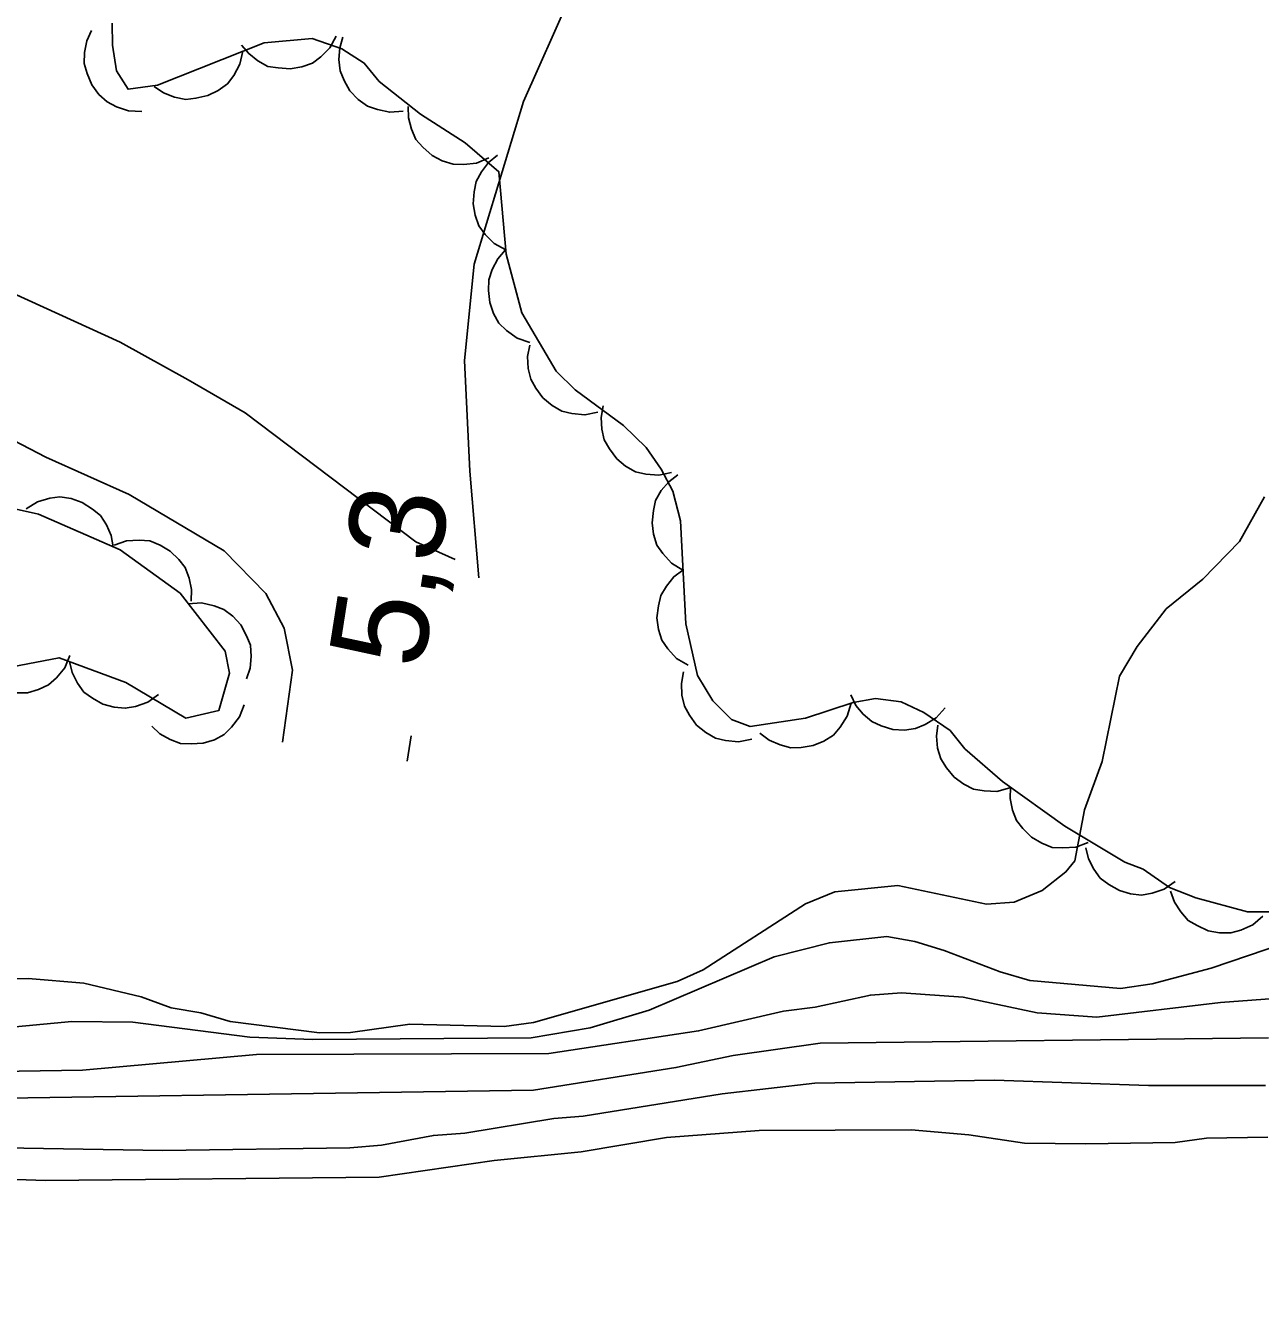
# Model space of a CAD drawing. Extents: x 282461 to 284471, y 5554090 to 5557646.
# Drawn here: x 283663.01 to 283701.79, y 5554643.6 to 5554684.09 of the extents above; entities that cross this region are included whole.
import ezdxf

# ---------------------------------------------------------------- set-up
doc = ezdxf.new("R2010")
doc.units = 0
for name, color, linetype in [('Niveau 1', 7, 'Continuous'), ('Niveau 2', 7, 'Continuous'), ('Niveau 21', 7, 'Continuous'), ('Niveau 22', 7, 'Continuous'), ('Niveau 3', 7, 'Continuous'), ('Niveau 4', 7, 'Continuous'), ('Niveau 44', 7, 'Continuous')]:
    doc.layers.add(name, color=color, linetype=linetype)

msp = doc.modelspace()

# ---------------------------------------------------------------- linework, layer by layer
at = {"layer": 'Niveau 1'}
for points in [[(283701.92, 5554669.28), (283701.13, 5554667.88), (283699.98, 5554666.7), (283698.83, 5554665.76), (283697.92, 5554664.58), (283697.36, 5554663.65), (283696.82, 5554660.97), (283696.26, 5554659.45), (283695.96, 5554657.85)], [(283695.96, 5554657.85), (283695.68, 5554657.5), (283694.93, 5554656.91), (283694.06, 5554656.55), (283693.19, 5554656.48), (283690.4, 5554657.07), (283688.42, 5554656.87), (283687.5, 5554656.5), (283684.28, 5554654.42), (283683.47, 5554654.06), (283678.96, 5554652.77), (283678.03, 5554652.64), (283675.07, 5554652.71), (283673.21, 5554652.45), (283672.23, 5554652.44), (283669.43, 5554652.8), (283668.5, 5554653.07), (283667.57, 5554653.23), (283666.63, 5554653.57), (283664.83, 5554654), (283663.08, 5554654.15), (283662.09, 5554654.13)]]:
    msp.add_lwpolyline(points, dxfattribs=at)
at = {"layer": 'Niveau 2'}
for points in [[(283686.52, 5554654.83), (283688.25, 5554655.27), (283690.05, 5554655.47), (283690.93, 5554655.31), (283691.86, 5554655.03), (283693.62, 5554654.36), (283694.55, 5554654.09), (283697.4, 5554653.84), (283698.39, 5554653.98), (283700.24, 5554654.47), (283702.56, 5554655.26)], [(283661.55, 5554652.53), (283664.45, 5554652.8), (283666.37, 5554652.78), (283670.04, 5554652.31), (283672.02, 5554652.23), (283678.88, 5554652.28), (283680.74, 5554652.6), (283682.59, 5554653.15), (283686.52, 5554654.83)], [(283702.51, 5554653.54), (283700.54, 5554653.4), (283696.65, 5554652.93), (283694.78, 5554653.07), (283692.45, 5554653.56), (283690.52, 5554653.7), (283689.54, 5554653.63), (283687.8, 5554653.25), (283686.81, 5554653.12), (283684.14, 5554652.5), (283679.44, 5554651.79), (283670.25, 5554651.76), (283664.79, 5554651.27), (283654.84, 5554651.11)], [(283618.87, 5554643.6), (283624.75, 5554643.69), (283625.68, 5554643.76), (283628.35, 5554644.21), (283631.08, 5554644.89), (283634.73, 5554646.06), (283636.53, 5554646.49), (283639.19, 5554647.35), (283641.63, 5554647.97), (283648.59, 5554649.12), (283649.58, 5554649.14), (283650.51, 5554649.27), (283656.84, 5554650.3), (283678.96, 5554650.64), (283683.43, 5554651.35), (283685.23, 5554651.73), (283687.96, 5554652.12), (283702.05, 5554652.28)], [(283639.04, 5554645.5), (283639.91, 5554645.98), (283641.76, 5554646.71), (283642.63, 5554646.96), (283648.27, 5554647.74), (283651.93, 5554648.38), (283653.85, 5554648.53), (283658.57, 5554648.6), (283660.43, 5554648.86), (283667.31, 5554648.74), (283673.19, 5554648.83), (283674.18, 5554648.91), (283675.81, 5554649.22), (283676.8, 5554649.29), (283679.59, 5554649.75), (283680.52, 5554649.82), (283684.88, 5554650.53), (283687.79, 5554650.86), (283693.44, 5554650.95), (283698.28, 5554650.79), (283701.95, 5554650.79)]]:
    msp.add_lwpolyline(points, dxfattribs=at)
at = {"layer": 'Niveau 21'}
for points in [[(283676.49, 5554667.31), (283675.26, 5554667.87), (283669.9, 5554671.92), (283668.11, 5554672.96), (283665.97, 5554674.14), (283659.58, 5554677.06), (283658.02, 5554678.02), (283655.37, 5554680.12), (283652.89, 5554682.77), (283651.39, 5554685.24), (283650.02, 5554687.8), (283647.98, 5554691.27), (283645.78, 5554694.75), (283644.23, 5554698.69), (283643.84, 5554701.79), (283643.75, 5554703.58), (283644.5, 5554706.87), (283645.42, 5554711.5), (283646.28, 5554714.98), (283646.43, 5554716.11), (283646.23, 5554717.72)], [(283661.85, 5554671.45), (283663.64, 5554670.53), (283666.25, 5554669.36), (283669.24, 5554667.59), (283670.55, 5554666.25), (283671.12, 5554665.16), (283671.38, 5554663.84), (283671.07, 5554661.58)]]:
    msp.add_lwpolyline(points, dxfattribs=at)
at = {"layer": 'Niveau 22'}
msp.add_lwpolyline([(283686.64, 5554730.93), (283688.98, 5554727.95), (283689.7, 5554726.46), (283689.72, 5554725.06), (283687.53, 5554717.49), (283686.92, 5554714.26), (283685.25, 5554707.12), (283683.94, 5554702.47), (283682.85, 5554698.05), (283681.96, 5554693.84), (283681.23, 5554688.15), (283680.1, 5554684.98), (283678.64, 5554681.71), (283677.09, 5554676.59), (283676.79, 5554673.57), (283676.96, 5554670.09), (283677.24, 5554666.74)], dxfattribs=at)
at = {"layer": 'Niveau 3'}
msp.add_line((283674.99, 5554660.98), (283675.11, 5554661.77), dxfattribs=at)
at = {"layer": 'Niveau 4'}
msp.add_lwpolyline([(283702.02, 5554649.16), (283700.1, 5554649.13), (283699.11, 5554649), (283696.31, 5554648.95), (283694.38, 5554648.98), (283692.63, 5554649.24), (283690.82, 5554649.39), (283686.04, 5554649.37), (283683.13, 5554649.15), (283680.45, 5554648.7), (283677.72, 5554648.43), (283674.11, 5554647.91), (283663.62, 5554647.8), (283660.29, 5554647.92)], dxfattribs=at)
at = {"layer": 'Niveau 44'}
for points in [[(283704.15, 5554656.24), (283701.39, 5554656.24), (283699.76, 5554656.68), (283698.94, 5554657.01), (283698.11, 5554657.58), (283697.53, 5554657.8), (283695.65, 5554658.94), (283693.69, 5554660.34), (283692.51, 5554661.37), (283692.04, 5554661.94), (283691.22, 5554662.51), (283690.51, 5554662.84), (283689.7, 5554662.95), (283689, 5554662.82), (283687.5, 5554662.33), (283685.76, 5554662.07), (283685.18, 5554662.29), (283684.59, 5554662.87), (283684.11, 5554663.67), (283683.74, 5554665.29), (283683.57, 5554668.53), (283683.33, 5554669.46), (283682.97, 5554670.15), (283682.49, 5554670.83), (283681.78, 5554671.52), (283680.26, 5554672.65), (283679.67, 5554673.23), (283678.59, 5554675.06), (283678.1, 5554676.91), (283677.87, 5554679.5), (283676.81, 5554680.41), (283675.4, 5554681.31), (283674.11, 5554682.33), (283673.64, 5554682.91), (283672.93, 5554683.36), (283672, 5554683.69), (283670.49, 5554683.55), (283667.14, 5554682.22), (283666.22, 5554682.09), (283665.86, 5554682.67), (283665.73, 5554683.48), (283665.72, 5554684.17)], [(283666.65, 5554681.39), (283666.23, 5554681.41), (283665.85, 5554681.54), (283665.56, 5554681.69), (283665.3, 5554681.93), (283665.08, 5554682.23), (283664.93, 5554682.59), (283664.84, 5554682.9), (283664.85, 5554683.25), (283664.92, 5554683.61), (283665.07, 5554683.94)], [(283672.76, 5554683.76), (283672.56, 5554683.39), (283672.27, 5554683.11), (283672.01, 5554682.91), (283671.68, 5554682.79), (283671.31, 5554682.73), (283670.93, 5554682.76), (283670.61, 5554682.81), (283670.3, 5554682.98), (283670.01, 5554683.21), (283669.78, 5554683.48)], [(283674.86, 5554681.4), (283674.44, 5554681.37), (283674.05, 5554681.45), (283673.74, 5554681.56), (283673.45, 5554681.77), (283673.19, 5554682.04), (283673.01, 5554682.37), (283672.88, 5554682.67), (283672.84, 5554683.02), (283672.87, 5554683.39), (283672.97, 5554683.73)], [(283669.82, 5554683.29), (283669.73, 5554682.88), (283669.54, 5554682.52), (283669.34, 5554682.26), (283669.05, 5554682.05), (283668.72, 5554681.89), (283668.35, 5554681.81), (283668.03, 5554681.77), (283667.68, 5554681.84), (283667.33, 5554681.98), (283667.04, 5554682.18)], [(283677.55, 5554679.94), (283677.16, 5554679.77), (283676.76, 5554679.73), (283676.43, 5554679.74), (283676.09, 5554679.84), (283675.77, 5554680.01), (283675.48, 5554680.27), (283675.26, 5554680.51), (283675.12, 5554680.84), (283675.03, 5554681.19), (283675.02, 5554681.55)], [(283678.09, 5554677.04), (283677.72, 5554677.24), (283677.44, 5554677.53), (283677.24, 5554677.8), (283677.12, 5554678.13), (283677.06, 5554678.49), (283677.09, 5554678.87), (283677.15, 5554679.19), (283677.32, 5554679.5), (283677.54, 5554679.79), (283677.82, 5554680.02)], [(283678.84, 5554674.13), (283678.44, 5554674.27), (283678.11, 5554674.51), (283677.87, 5554674.74), (283677.7, 5554675.04), (283677.58, 5554675.39), (283677.54, 5554675.77), (283677.55, 5554676.1), (283677.66, 5554676.43), (283677.83, 5554676.76), (283678.07, 5554677.03)], [(283680.98, 5554671.94), (283680.57, 5554671.86), (283680.16, 5554671.9), (283679.84, 5554671.98), (283679.54, 5554672.15), (283679.25, 5554672.39), (283679.03, 5554672.7), (283678.87, 5554672.98), (283678.79, 5554673.32), (283678.77, 5554673.69), (283678.84, 5554674.05)], [(283683.29, 5554670.05), (283682.89, 5554669.96), (283682.48, 5554670), (283682.16, 5554670.07), (283681.85, 5554670.25), (283681.57, 5554670.48), (283681.34, 5554670.79), (283681.18, 5554671.07), (283681.1, 5554671.41), (283681.08, 5554671.78), (283681.14, 5554672.14)], [(283683.65, 5554666.98), (283683.29, 5554667.2), (283683.02, 5554667.5), (283682.83, 5554667.77), (283682.73, 5554668.11), (283682.68, 5554668.47), (283682.72, 5554668.85), (283682.79, 5554669.17), (283682.97, 5554669.48), (283683.21, 5554669.76), (283683.49, 5554669.98)], [(283650.15, 5554662.39), (283649.99, 5554665.17), (283650.66, 5554666.92), (283651.8, 5554668.33), (283655.26, 5554669.43), (283657.7, 5554669.58), (283660.49, 5554669.39), (283663.4, 5554668.74), (283665.97, 5554667.62), (283667.85, 5554666.26), (283669.27, 5554664.43), (283669.4, 5554663.74), (283669.07, 5554662.57), (283668.03, 5554662.33), (283666.15, 5554663.45), (283664.05, 5554664.23), (283662.08, 5554663.85), (283657.93, 5554662.4), (283655.86, 5554661.09), (283654.02, 5554659.67), (283652.29, 5554658.83), (283651, 5554659.51), (283650.15, 5554662.39)], [(283663.02, 5554668.91), (283663.37, 5554669.13), (283663.76, 5554669.24), (283664.08, 5554669.28), (283664.43, 5554669.23), (283664.78, 5554669.11), (283665.1, 5554668.9), (283665.35, 5554668.7), (283665.54, 5554668.4), (283665.69, 5554668.07), (283665.75, 5554667.71)], [(283665.78, 5554667.76), (283666.17, 5554667.9), (283666.57, 5554667.92), (283666.9, 5554667.9), (283667.23, 5554667.77), (283667.54, 5554667.58), (283667.81, 5554667.31), (283668.01, 5554667.06), (283668.14, 5554666.73), (283668.21, 5554666.37), (283668.2, 5554666.01)], [(283683.81, 5554663.99), (283683.45, 5554664.2), (283683.18, 5554664.51), (283682.99, 5554664.78), (283682.88, 5554665.11), (283682.83, 5554665.48), (283682.88, 5554665.86), (283682.95, 5554666.18), (283683.13, 5554666.48), (283683.36, 5554666.77), (283683.65, 5554666.98)], [(283668.11, 5554665.92), (283668.53, 5554665.95), (283668.92, 5554665.86), (283669.23, 5554665.74), (283669.51, 5554665.53), (283669.76, 5554665.26), (283669.94, 5554664.92), (283670.06, 5554664.62), (283670.09, 5554664.27), (283670.05, 5554663.9), (283669.94, 5554663.56)], [(283664.39, 5554664.3), (283664.23, 5554663.91), (283663.97, 5554663.6), (283663.72, 5554663.38), (283663.41, 5554663.23), (283663.06, 5554663.13), (283662.67, 5554663.12), (283662.35, 5554663.15), (283662.03, 5554663.28), (283661.71, 5554663.48), (283661.46, 5554663.73)], [(283667.17, 5554663.07), (283666.84, 5554662.83), (283666.45, 5554662.7), (283666.13, 5554662.64), (283665.78, 5554662.67), (283665.43, 5554662.77), (283665.1, 5554662.96), (283664.83, 5554663.15), (283664.63, 5554663.43), (283664.46, 5554663.76), (283664.38, 5554664.11)], [(283685.81, 5554661.67), (283685.4, 5554661.59), (283684.99, 5554661.63), (283684.67, 5554661.7), (283684.37, 5554661.88), (283684.08, 5554662.11), (283683.86, 5554662.42), (283683.7, 5554662.71), (283683.62, 5554663.05), (283683.6, 5554663.42), (283683.67, 5554663.78)], [(283691.89, 5554662.65), (283691.61, 5554662.34), (283691.26, 5554662.13), (283690.96, 5554662), (283690.61, 5554661.95), (283690.24, 5554661.97), (283689.88, 5554662.09), (283689.58, 5554662.22), (283689.31, 5554662.45), (283689.08, 5554662.73), (283688.92, 5554663.06)], [(283669.87, 5554662.75), (283669.72, 5554662.37), (283669.47, 5554662.05), (283669.24, 5554661.82), (283668.93, 5554661.65), (283668.58, 5554661.54), (283668.2, 5554661.52), (283667.87, 5554661.53), (283667.54, 5554661.66), (283667.22, 5554661.84), (283666.96, 5554662.08)], [(283688.93, 5554662.8), (283688.81, 5554662.39), (283688.59, 5554662.05), (283688.38, 5554661.8), (283688.08, 5554661.61), (283687.74, 5554661.47), (283687.36, 5554661.41), (283687.04, 5554661.4), (283686.7, 5554661.49), (283686.36, 5554661.64), (283686.07, 5554661.86)], [(283693.92, 5554660.14), (283693.51, 5554660.03), (283693.11, 5554660.05), (283692.78, 5554660.1), (283692.47, 5554660.26), (283692.17, 5554660.48), (283691.93, 5554660.77), (283691.75, 5554661.05), (283691.65, 5554661.39), (283691.62, 5554661.76), (283691.66, 5554662.11)], [(283696.38, 5554658.42), (283695.99, 5554658.28), (283695.58, 5554658.25), (283695.25, 5554658.27), (283694.92, 5554658.4), (283694.6, 5554658.59), (283694.33, 5554658.86), (283694.13, 5554659.11), (283694, 5554659.44), (283693.93, 5554659.8), (283693.94, 5554660.16)], [(283699.11, 5554657.2), (283698.77, 5554656.96), (283698.39, 5554656.83), (283698.06, 5554656.77), (283697.71, 5554656.81), (283697.36, 5554656.91), (283697.03, 5554657.1), (283696.76, 5554657.3), (283696.56, 5554657.58), (283696.39, 5554657.91), (283696.31, 5554658.26)], [(283701.87, 5554656.11), (283701.55, 5554655.84), (283701.18, 5554655.67), (283700.86, 5554655.58), (283700.51, 5554655.58), (283700.15, 5554655.65), (283699.8, 5554655.81), (283699.52, 5554655.97), (283699.29, 5554656.24), (283699.09, 5554656.55), (283698.97, 5554656.89)]]:
    msp.add_lwpolyline(points, dxfattribs=at)

# ---------------------------------------------------------------- texts
at = {"layer": 'Niveau 3'}
msp.add_text('5,3  ', height=3, rotation=81.0957, dxfattribs=at).set_placement((283675.47, 5554663.82))

doc.saveas('drawing.dxf')
